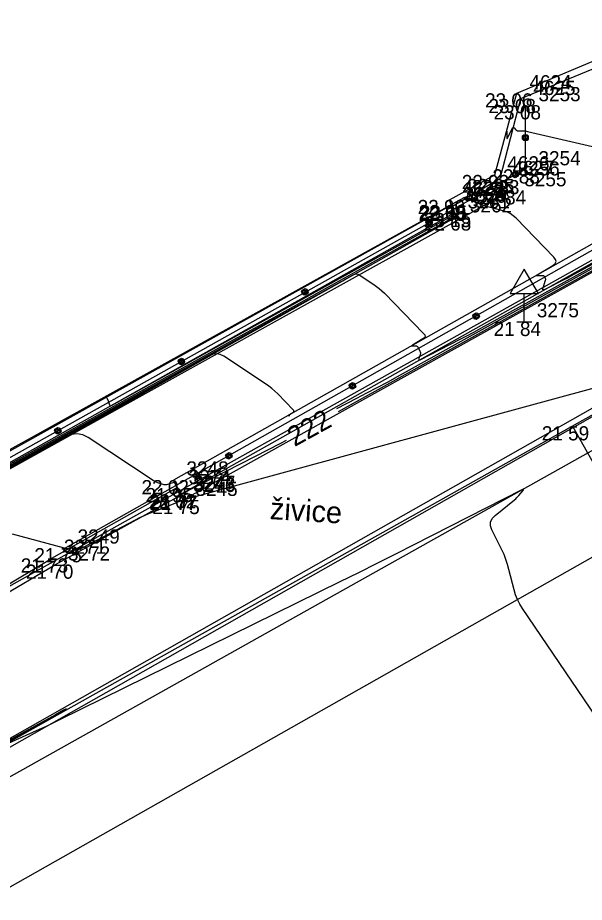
# Model space of a CAD drawing. Extents: x -702257 to -701487, y -1009871 to -1008841.
# Drawn here: x -701977.44 to -701967.44, y -1009621.47 to -1009605.88 of the extents above; entities that cross this region are included whole.
import ezdxf

# ---------------------------------------------------------------- set-up
doc = ezdxf.new("R2010")
doc.units = 0
for name, color, linetype in [('Ex_Contour Labels', 7, 'Continuous'), ('Ex_Major Contours', 7, 'Continuous'), ('Ex_Minor Contours', 7, 'Continuous'), ('Z_betonova_konstrukce', 7, 'Continuous'), ('Z_body', 7, 'Continuous'), ('Z_body_cisla', 7, 'Continuous'), ('Z_body_vysky_redukovane', 7, 'Continuous'), ('Z_dopravni_znacky', 7, 'Continuous'), ('Z_katastr_hranice', 7, 'Continuous'), ('Z_komunikace', 7, 'Continuous'), ('Z_obruba', 7, 'Continuous'), ('Z_popisy', 7, 'Continuous'), ('Z_rozhranni', 7, 'Continuous'), ('Z_zabradli', 7, 'Continuous'), ('Z_zabradli_znaky', 7, 'Continuous')]:
    doc.layers.add(name, color=color, linetype=linetype)

# ---------------------------------------------------------------- blocks, each defined once
blk = doc.blocks.new('POINT_DISPLAY')
blk.add_line((0, 0), (0, 0))
blk = doc.blocks.new('Z527')
for p, q in [((0, 0.93), (-0.25, 0.5)), ((0.25, 0.5), (0, 0.93)), ((-0.25, 0.5), (0.25, 0.5)), ((0, 0), (0, 0.5)), ((-0.13, 0), (0.13, 0))]:
    blk.add_line(p, q)
blk = doc.blocks.new('Z530')
for p, q in [((-0.05, 0.03), (-0.03, 0.05)), ((-0.05, -0.03), (-0.05, 0.03)), ((-0.03, 0.05), (0.03, 0.05)), ((-0.03, -0.03), (-0.03, 0.03)), ((-0.03, 0.03), (0.03, 0.03)), ((-0.03, -0.03), (0.03, 0.03)), ((0.03, 0.05), (0.05, 0.03)), ((0.03, 0.03), (0.03, -0.03)), ((0.05, 0.03), (0.05, -0.03)), ((-0.03, -0.05), (-0.05, -0.03)), ((0.03, -0.03), (-0.03, -0.03)), ((0.03, -0.05), (-0.03, -0.05)), ((0.05, -0.03), (0.03, -0.05))]:
    blk.add_line(p, q)

msp = doc.modelspace()

# ---------------------------------------------------------------- linework, layer by layer
at = {"layer": 'Ex_Major Contours'}
for points in [[(-701968.81, -1009607.875), (-701968.81, -1009607.987), (-701968.809, -1009608.001), (-701968.806, -1009608.007), (-701968.8, -1009608.004), (-701968.793, -1009607.991), (-701968.706, -1009607.821), (-701968.7, -1009607.813), (-701968.694, -1009607.81), (-701968.688, -1009607.812), (-701968.681, -1009607.818), (-701968.651, -1009607.854), (-701968.643, -1009607.862), (-701968.634, -1009607.868), (-701968.624, -1009607.871), (-701968.613, -1009607.872), (-701968.519, -1009607.872), (-701968.5, -1009607.873), (-701968.48, -1009607.874), (-701968.461, -1009607.877), (-701968.442, -1009607.881), (-701966.916, -1009608.235)], [(-701965.795, -1009609.506), (-701971.781, -1009612.824)], [(-701972.701, -1009613.331), (-701972.811, -1009613.39), (-701973.028, -1009613.505), (-701973.246, -1009613.617), (-701974.556, -1009614.287), (-701974.558, -1009614.286), (-701974.561, -1009614.281), (-701974.678, -1009614.056), (-701974.679, -1009614.055), (-701974.677, -1009614.066), (-701974.677, -1009614.068), (-701974.677, -1009614.069), (-701974.678, -1009614.07), (-701974.68, -1009614.071), (-701974.793, -1009614.107), (-701974.812, -1009614.111), (-701974.831, -1009614.113), (-701974.851, -1009614.111), (-701974.87, -1009614.106), (-701974.963, -1009614.076), (-701974.985, -1009614.068), (-701975.005, -1009614.059), (-701975.026, -1009614.049), (-701975.045, -1009614.037), (-701976.192, -1009613.281), (-701976.289, -1009613.232), (-701976.387, -1009613.214), (-701976.487, -1009613.225), (-701976.587, -1009613.267), (-701976.99, -1009613.494), (-701977.091, -1009613.551), (-701977.192, -1009613.608), (-701977.293, -1009613.664), (-701977.395, -1009613.72), (-701979.437, -1009614.853)]]:
    msp.add_lwpolyline(points, dxfattribs=at)
msp.add_lwpolyline([(-701975.812, -1009612.712), (-701975.804, -1009612.718), (-701975.795, -1009612.719), (-701975.783, -1009612.714), (-701969.743, -1009609.353), (-701969.732, -1009609.346), (-701969.727, -1009609.336), (-701969.727, -1009609.326), (-701969.731, -1009609.313), (-701969.769, -1009609.243), (-701969.779, -1009609.223), (-701969.793, -1009609.197), (-701969.797, -1009609.192), (-701969.801, -1009609.189), (-701969.807, -1009609.189), (-701969.813, -1009609.191), (-701975.859, -1009612.561), (-701975.864, -1009612.565), (-701975.867, -1009612.569), (-701975.867, -1009612.575), (-701975.865, -1009612.581), (-701975.851, -1009612.607), (-701975.848, -1009612.614), (-701975.845, -1009612.62), (-701975.842, -1009612.627), (-701975.839, -1009612.634), (-701975.817, -1009612.701)], close=True, dxfattribs=at)
at = {"layer": 'Ex_Minor Contours'}
for points in [[(-701966.076, -1009609.547), (-701967.552, -1009610.366), (-701967.615, -1009610.4), (-701967.678, -1009610.434), (-701967.741, -1009610.467), (-701967.805, -1009610.5), (-701968.138, -1009610.671), (-701968.158, -1009610.678), (-701968.171, -1009610.676), (-701968.174, -1009610.665), (-701968.17, -1009610.643), (-701968.124, -1009610.502), (-701968.123, -1009610.494), (-701968.123, -1009610.486), (-701968.124, -1009610.478), (-701968.127, -1009610.471), (-701968.143, -1009610.441), (-701968.147, -1009610.434), (-701968.153, -1009610.43), (-701968.159, -1009610.427), (-701968.167, -1009610.426), (-701968.27, -1009610.43), (-701968.285, -1009610.429), (-701968.291, -1009610.426), (-701968.288, -1009610.42), (-701968.275, -1009610.411), (-701967.997, -1009610.246), (-701967.956, -1009610.213), (-701967.94, -1009610.178), (-701967.947, -1009610.139), (-701967.977, -1009610.097), (-701968.646, -1009609.412), (-701968.696, -1009609.368), (-701968.75, -1009609.331), (-701968.809, -1009609.302), (-701968.872, -1009609.281), (-701969.234, -1009609.187), (-701969.249, -1009609.182), (-701969.265, -1009609.176), (-701969.279, -1009609.169), (-701969.293, -1009609.161), (-701969.353, -1009609.123), (-701969.364, -1009609.115), (-701969.374, -1009609.106), (-701969.383, -1009609.095), (-701969.39, -1009609.083), (-701969.417, -1009609.033), (-701969.424, -1009609.023), (-701969.433, -1009609.017), (-701969.444, -1009609.015), (-701969.457, -1009609.017), (-701969.533, -1009609.042), (-701969.55, -1009609.048), (-701969.567, -1009609.055), (-701969.583, -1009609.062), (-701969.599, -1009609.07), (-701969.786, -1009609.168), (-701969.789, -1009609.17), (-701969.791, -1009609.173), (-701969.791, -1009609.176), (-701969.791, -1009609.179), (-701969.788, -1009609.193), (-701969.786, -1009609.2), (-701969.783, -1009609.207), (-701969.718, -1009609.33), (-701969.703, -1009609.357), (-701969.701, -1009609.364), (-701969.701, -1009609.37), (-701969.704, -1009609.374), (-701969.709, -1009609.379), (-701972.118, -1009610.719), (-701972.522, -1009610.943), (-701972.926, -1009611.168), (-701973.33, -1009611.392), (-701973.734, -1009611.616), (-701979.232, -1009614.666)], [(-701978.597, -1009614.338), (-701971.729, -1009610.529), (-701971.703, -1009610.514), (-701971.676, -1009610.499), (-701971.649, -1009610.484), (-701971.622, -1009610.469), (-701971.516, -1009610.409), (-701971.489, -1009610.398), (-701971.463, -1009610.395), (-701971.437, -1009610.4), (-701971.411, -1009610.413), (-701971.156, -1009610.581), (-701971.106, -1009610.616), (-701971.058, -1009610.653), (-701971.012, -1009610.693), (-701970.968, -1009610.736), (-701970.276, -1009611.444), (-701970.256, -1009611.471), (-701970.251, -1009611.497), (-701970.262, -1009611.52), (-701970.289, -1009611.542), (-701970.472, -1009611.65), (-701970.48, -1009611.656), (-701970.483, -1009611.66), (-701970.479, -1009611.662), (-701970.469, -1009611.663), (-701970.416, -1009611.661), (-701970.404, -1009611.662), (-701970.394, -1009611.666), (-701970.385, -1009611.673), (-701970.378, -1009611.683), (-701970.341, -1009611.754), (-701970.335, -1009611.77), (-701970.332, -1009611.786), (-701970.332, -1009611.802), (-701970.336, -1009611.819), (-701970.358, -1009611.889), (-701970.361, -1009611.903), (-701970.359, -1009611.91), (-701970.351, -1009611.912), (-701970.337, -1009611.907), (-701969.633, -1009611.547), (-701969.511, -1009611.484), (-701969.389, -1009611.419), (-701969.268, -1009611.354), (-701969.147, -1009611.288), (-701966.171, -1009609.638)], [(-701965.983, -1009609.572), (-701970.742, -1009612.21), (-701970.921, -1009612.308), (-701971.1, -1009612.405), (-701971.281, -1009612.5), (-701971.462, -1009612.593), (-701971.81, -1009612.771)], [(-701972.636, -1009612.895), (-701972.636, -1009612.895), (-701972.642, -1009612.895), (-701972.667, -1009612.896), (-701972.672, -1009612.895), (-701972.674, -1009612.894), (-701972.673, -1009612.892), (-701972.669, -1009612.89), (-701972.581, -1009612.838), (-701972.568, -1009612.827), (-701972.563, -1009612.816), (-701972.565, -1009612.804), (-701972.575, -1009612.791), (-701972.848, -1009612.512), (-701972.899, -1009612.462), (-701972.952, -1009612.415), (-701973.008, -1009612.372), (-701973.067, -1009612.331), (-701973.802, -1009611.847), (-701973.863, -1009611.816), (-701973.925, -1009611.804), (-701973.988, -1009611.812), (-701974.051, -1009611.838), (-701974.306, -1009611.982), (-701974.37, -1009612.018), (-701974.434, -1009612.053), (-701974.498, -1009612.089), (-701974.562, -1009612.124), (-701979.017, -1009614.596)], [(-701977.532, -1009614.978), (-701976.619, -1009615.225), (-701976.611, -1009615.228), (-701976.607, -1009615.233), (-701976.607, -1009615.239), (-701976.61, -1009615.247), (-701976.63, -1009615.28), (-701976.633, -1009615.288), (-701976.633, -1009615.292), (-701976.629, -1009615.294), (-701976.621, -1009615.294), (-701976.418, -1009615.262), (-701976.381, -1009615.254), (-701976.346, -1009615.244), (-701976.311, -1009615.231), (-701976.278, -1009615.215), (-701975.36, -1009614.733), (-701975.279, -1009614.692), (-701975.197, -1009614.653), (-701975.113, -1009614.616), (-701975.029, -1009614.581), (-701974.69, -1009614.447), (-701974.604, -1009614.415), (-701974.518, -1009614.385), (-701974.432, -1009614.357), (-701974.344, -1009614.332), (-701966.923, -1009612.309)], [(-701966.789, -1009618.856), (-701968.531, -1009616.297), (-701968.579, -1009616.219), (-701968.621, -1009616.138), (-701968.654, -1009616.053), (-701968.68, -1009615.964), (-701968.77, -1009615.605), (-701968.795, -1009615.516), (-701968.824, -1009615.428), (-701968.858, -1009615.343), (-701968.897, -1009615.259), (-701969.071, -1009614.907), (-701969.095, -1009614.836), (-701969.094, -1009614.77), (-701969.068, -1009614.71), (-701969.016, -1009614.655), (-701968.672, -1009614.376), (-701968.652, -1009614.358), (-701968.632, -1009614.34), (-701968.614, -1009614.321), (-701968.596, -1009614.3), (-701968.527, -1009614.217), (-701968.515, -1009614.201), (-701968.514, -1009614.192), (-701968.522, -1009614.192), (-701968.541, -1009614.2), (-701970.448, -1009615.17), (-701970.774, -1009615.335), (-701971.1, -1009615.5), (-701971.427, -1009615.663), (-701971.755, -1009615.825), (-701976.698, -1009618.259), (-701976.817, -1009618.316), (-701976.936, -1009618.373), (-701977.055, -1009618.428), (-701977.175, -1009618.482), (-701977.656, -1009618.697)], [(-701977.667, -1009618.676), (-701976.769, -1009618.171), (-701976.628, -1009618.091), (-701976.581, -1009618.064), (-701976.629, -1009618.089), (-701976.771, -1009618.167), (-701978.422, -1009619.073)]]:
    msp.add_lwpolyline(points, dxfattribs=at)
at = {"layer": 'Z_betonova_konstrukce'}
for p, q in [((-701969.8, -1009609.18), (-701979.95, -1009614.81)), ((-701979.92, -1009614.82), (-701969.8, -1009609.19)), ((-701965.95, -1009609.1), (-701974.69, -1009614.03)), ((-701969.69, -1009609.38), (-701969.8, -1009609.18)), ((-701969.8, -1009609.19), (-701969.73, -1009609.32)), ((-701969.73, -1009609.32), (-701979.86, -1009615)), ((-701979.84, -1009615.1), (-701969.69, -1009609.38)), ((-701974.56, -1009614.28), (-701965.83, -1009609.37)), ((-701974.52, -1009614.38), (-701965.72, -1009609.48)), ((-701974.69, -1009614.03), (-701974.56, -1009614.28)), ((-701974.56, -1009614.31), (-701974.69, -1009614.03)), ((-701974.56, -1009614.28), (-701974.56, -1009614.31)), ((-701974.52, -1009614.38), (-701974.56, -1009614.31))]:
    msp.add_line(p, q, dxfattribs=at)
at = {"layer": 'Z_katastr_hranice'}
for p, q in [((-702014.27, -1009636.43), (-701959.3, -1009605.67)), ((-702013.06, -1009638.53), (-701957.87, -1009607.59))]:
    msp.add_line(p, q, dxfattribs=at)
at = {"layer": 'Z_komunikace'}
msp.add_line((-701966.34, -1009612.97), (-701980.98, -1009621.17), dxfattribs=at)
at = {"layer": 'Z_obruba'}
for p, q in [((-701968.63, -1009607.21), (-701966.58, -1009606.34)), ((-701966.6, -1009606.5), (-701968.57, -1009607.31)), ((-701969.02, -1009608.65), (-701968.63, -1009607.21)), ((-701968.57, -1009607.31), (-701968.93, -1009608.72)), ((-701969.82, -1009609.09), (-701969.02, -1009608.65)), ((-701968.93, -1009608.72), (-701969.78, -1009609.21)), ((-701969.78, -1009609.21), (-701969.82, -1009609.09)), ((-701966.68, -1009612.41), (-701981.25, -1009620.67)), ((-701981.19, -1009620.79), (-701966.6, -1009612.51)), ((-701974.64, -1009614.17), (-701976.84, -1009615.41)), ((-701974.64, -1009614.17), (-701974.57, -1009614.3)), ((-701976.77, -1009615.52), (-701974.57, -1009614.3)), ((-701978.55, -1009616.43), (-701976.84, -1009615.41)), ((-701978.48, -1009616.52), (-701976.77, -1009615.52))]:
    msp.add_line(p, q, dxfattribs=at)
at = {"layer": 'Z_rozhranni'}
for p, q in [((-701967.65, -1009613.08), (-701966.58, -1009614.98)), ((-701966.58, -1009614.98), (-701978.09, -1009621.5))]:
    msp.add_line(p, q, dxfattribs=at)
at = {"layer": 'Z_zabradli'}
for p, q in [((-701968.48, -1009608.55), (-701968.48, -1009607.42)), ((-701968.84, -1009608.74), (-701968.48, -1009608.55)), ((-701980, -1009614.99), (-701968.84, -1009608.74)), ((-701968.84, -1009608.74), (-701968.72, -1009608.92)), ((-701968.72, -1009608.92), (-701978.65, -1009614.43)), ((-701966.09, -1009609.29), (-701976.6, -1009615.23))]:
    msp.add_line(p, q, dxfattribs=at)

# ---------------------------------------------------------------- block references
at = {"layer": 'Z_body'}
for p in [(-701968.63, -1009607.21), (-701968.57, -1009607.31), (-701968.48, -1009607.42), (-701968.48, -1009608.55), (-701969.02, -1009608.65), (-701968.93, -1009608.72), (-701968.84, -1009608.74), (-701968.72, -1009608.92), (-701969.82, -1009609.09), (-701969.8, -1009609.18), (-701969.8, -1009609.19), (-701969.78, -1009609.21), (-701969.73, -1009609.32), (-701969.69, -1009609.38), (-701968.5, -1009611.24), (-701967.65, -1009613.08), (-701974.69, -1009614.03), (-701974.64, -1009614.17), (-701974.57, -1009614.3), (-701974.56, -1009614.28), (-701974.56, -1009614.31), (-701974.52, -1009614.38), (-701976.6, -1009615.23), (-701976.84, -1009615.41), (-701976.77, -1009615.52)]:
    msp.add_blockref('POINT_DISPLAY', p, dxfattribs=at)
at = {"layer": 'Z_dopravni_znacky'}
msp.add_blockref('Z527', (-701968.5, -1009611.24), dxfattribs=at)
at = {"layer": 'Z_zabradli_znaky'}
for p, rotation in [((-701968.48, -1009607.99), -90.00000000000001), ((-701968.66, -1009608.64), -152.20000000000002), ((-701970.18, -1009609.49), 29.300000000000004), ((-701972.37, -1009610.71), 29.300000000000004), ((-701969.35, -1009611.14), 29.499999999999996), ((-701974.55, -1009611.94), 29.300000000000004), ((-701971.53, -1009612.37), 29.499999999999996), ((-701976.73, -1009613.16), 29.300000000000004), ((-701973.71, -1009613.6), 29.499999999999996)]:
    msp.add_blockref('Z530', p, dxfattribs=dict(at, rotation=rotation))

# ---------------------------------------------------------------- texts
at = {"layer": 'Ex_Contour Labels'}
msp.add_text('222', height=0.35, rotation=28.8581, dxfattribs=at).set_placement((-701972.553, -1009613.449))
at = {"layer": 'Z_body_cisla'}
for s, p in [('4624', (-701968.41, -1009607.14)), ('4625', (-701968.34, -1009607.24)), ('3253', (-701968.25, -1009607.35)), ('3254', (-701968.25, -1009608.48)), ('4626', (-701968.8, -1009608.57)), ('4627', (-701968.71, -1009608.65)), ('3256', (-701968.62, -1009608.66)), ('3255', (-701968.5, -1009608.85)), ('4628', (-701969.59, -1009609.02)), ('3263', (-701969.58, -1009609.11)), ('3264', (-701969.58, -1009609.11)), ('4629', (-701969.55, -1009609.14)), ('3261', (-701969.5, -1009609.24)), ('3262', (-701969.46, -1009609.31)), ('3275', (-701968.28, -1009611.16)), ('3248', (-701974.46, -1009613.95)), ('3274', (-701974.42, -1009614.1)), ('3247', (-701974.34, -1009614.2)), ('3273', (-701974.34, -1009614.23)), ('3246', (-701974.34, -1009614.24)), ('3245', (-701974.3, -1009614.31)), ('3249', (-701976.38, -1009615.15)), ('3271', (-701976.62, -1009615.33)), ('3272', (-701976.55, -1009615.45))]:
    msp.add_text(s, height=0.25, dxfattribs=at).set_placement(p)
at = {"layer": 'Z_body_vysky_redukovane'}
for s, p in [('23 06', (-701969.193, -1009607.46)), ('23 08', (-701969.132, -1009607.56)), ('23 08', (-701969.042, -1009607.67)), ('22 88', (-701969.063, -1009608.8)), ('22 93', (-701969.603, -1009608.9)), ('22 85', (-701969.513, -1009608.97)), ('22 83', (-701969.423, -1009608.99)), ('22 84', (-701969.303, -1009609.17)), ('22 90', (-701970.382, -1009609.34)), ('22 68', (-701970.363, -1009609.46)), ('22 90', (-701970.363, -1009609.43)), ('23 15', (-701970.342, -1009609.44)), ('22 68', (-701970.273, -1009609.63)), ('23 15', (-701970.272, -1009609.57)), ('21 84', (-701969.042, -1009611.49)), ('21 59', (-701968.192, -1009613.33)), ('22 02', (-701975.252, -1009614.28)), ('21 95', (-701975.182, -1009614.42)), ('22 02', (-701975.123, -1009614.53)), ('21 77', (-701975.112, -1009614.55)), ('21 77', (-701975.102, -1009614.56)), ('21 75', (-701975.062, -1009614.63)), ('21 75', (-701977.142, -1009615.48)), ('21 73', (-701977.382, -1009615.66)), ('21 70', (-701977.291, -1009615.77))]:
    msp.add_text(s, height=0.25, dxfattribs=at).set_placement(p)
at = {"layer": 'Z_popisy'}
msp.add_text('živice', height=0.38, rotation=356.4, dxfattribs=at).set_placement((-701972.995, -1009614.717))

doc.saveas('drawing.dxf')
